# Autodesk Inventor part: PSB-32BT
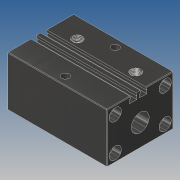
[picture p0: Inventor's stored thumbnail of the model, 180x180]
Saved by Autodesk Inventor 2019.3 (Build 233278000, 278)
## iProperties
Created: 2010-02
Part Number: PSB-32BT
Material: Ogólny
Document SubType Name: Modeling
Designer: CADENGINEERING4
Density: 1 g/cm^3
Appearance: Ciemnoszara
Author: CADENGINEERING4
Revision Number: 1LAST_VERSION
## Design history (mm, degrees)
feature "Baza1"
sketch "Szkic1"
  geometry: C1 r 3.4 at (52, 7) reference; C2 r 3.4 at (52, 37) reference; C3 r 3.4 at (7, 37) reference; C4 r 3.4 at (7, 7) reference; 1 further point
sketch "Szkic2"
  geometry: L1 (56.833, 41.876)-(47.308, 41.876); L2 (47.308, 41.876)-(47.308, 1.5); L3 (47.308, 1.5)-(56.833, 1.5); L4 (56.833, 1.5)-(56.833, 41.876); L5 (11.594, 41.485)-(1.93, 41.485); L6 (1.93, 41.485)-(1.93, 1.984); L7 (1.93, 1.984)-(11.594, 1.984); L8 (11.594, 1.984)-(11.594, 41.485); 1 further point
  constraints: 16 end point, 4 parallel, 2 horizontal, 2 perpendicular
extrude "Wyciągnięcie proste1" join sketch "Szkic2" distance "d0" = 25; taper "d1" = 0 deg
hole "Otwór1" sketch "Szkic1" diameter "d2" = 6.647; stored, may be unused: countersink angle "d6" = 90 deg, drill point angle "d8" = 118 deg; dims "d3" = 25, "d4" = 4, "d5" = 2, "d7" = 8
node "Bryła1"
